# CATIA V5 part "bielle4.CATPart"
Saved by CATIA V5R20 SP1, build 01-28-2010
Part number: Part1.1.2.3.4
Bounding box of the stored display mesh (mm): x 43 to 87, y 0 to 5, z 28.093 to 41.907
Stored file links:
  E:\EDELI\gcausse\Edeli_2012_686_gcausse\bielle4.CATPart
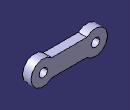
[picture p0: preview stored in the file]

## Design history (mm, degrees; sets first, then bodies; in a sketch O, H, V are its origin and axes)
Parameters
  long = 0.03
  diamtrou = 0.005
Body1 (main body)
  Sketch1 on zx-plane, origin (0, 0, 0), H (-1, 0, 0), V (0, 0, 1)
    line L1 (-54.899, 40) -> (-75.101, 40)
    line L2 (-54.899, 30) -> (-75.101, 30)
    arc A1 centre (-50, 35) radius 7 from (-54.899, 40) to (-54.899, 30) cw
    point P5 (-50, 35)
    point P6 (-45.101, 30)
    arc A2 centre (-80, 35) radius 7 from (-75.101, 40) to (-75.101, 30) ccw
    point P7 (-80, 35)
    circle A3 centre (-50, 35) radius 2.5
    distance P7 L1 = 5
    distance P5 L2 = 5
    distance L2 L1 = 10
    radius A1 = 7
    radius A2 = 7
    distance P5 P7 = 30 {= long}
    radius A3 = 2.5
    horizontal: L1 H, L2 H
    coincidence: A1 P6, P6 L2
  Pad1: profile Sketch1, direction (0, 1, 0), length 5
  Sketch2 on end face of Pad1, origin (0, 5, 0), H (-1, 0, 0), V (0, 0, 1)
    circle A1 centre (-80, 35) radius 2.5
    reference projected arc E1 centre (-80, 35) radius 7 from (-75.101, 40) to (-75.101, 30) ccw from edge [face of Pad1 from Sketch1.A2 | end face of Pad1]
    reference projected arc E2 centre (-80, 35) radius 7 from (-75.101, 40) to (-75.101, 30) ccw from edge [face of Pad1 from Sketch1.A2 | end face of Pad1]
    radius A1 = 2.5
    radius E2 = 7 (reference)
    concentricity: A1 E1
  Pocket1: profile Sketch2, direction (0, -1, 0), length 5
